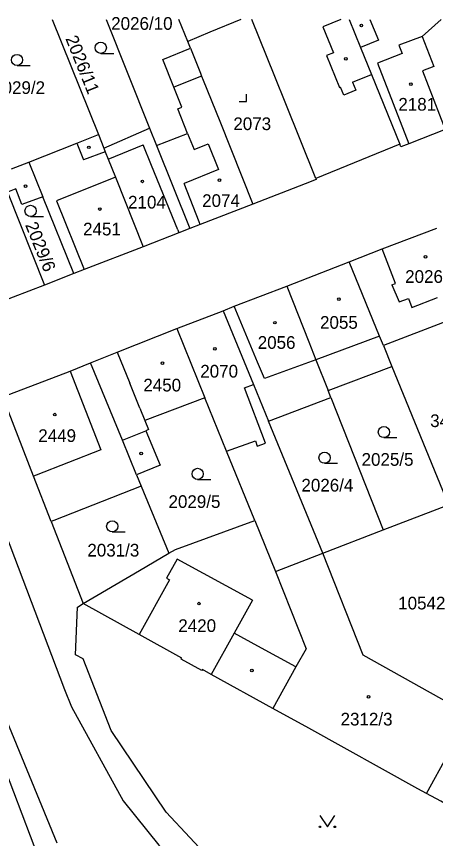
# Model space of a CAD drawing. Extents: x -564952 to -564307, y -1202373 to -1201847.
# Drawn here: x -564666.6 to -564610.5, y -1201959.8 to -1201849.7 of the extents above; entities that cross this region are included whole.
import ezdxf

# ---------------------------------------------------------------- set-up
doc = ezdxf.new("R2010")
doc.units = 0
for name, color, linetype in [('Hranice parcel', 7, 'Continuous'), ('Parcelní čísla', 7, 'Continuous'), ('Vnitřní kresba', 7, 'Continuous'), ('Značky budov', 7, 'Continuous'), ('Značky kultur', 7, 'Continuous')]:
    doc.layers.add(name, color=color, linetype=linetype)

msp = doc.modelspace()

# ---------------------------------------------------------------- linework, layer by layer
at = {"layer": 'Hranice parcel'}
for p, q in [((-564661.81, -1201850.07), (-564655.61, -1201865.52)), ((-564654.61, -1201850.07), (-564648.79, -1201864.64)), ((-564643.69, -1201853.02), (-564644.88, -1201850.07)), ((-564643.32, -1201853.94), (-564643.69, -1201853.02)), ((-564619.09, -1201857.46), (-564615.32, -1201866.78)), ((-564654.9, -1201867.35), (-564648.79, -1201864.64)), ((-564648.79, -1201864.64), (-564647.86, -1201866.96)), ((-564655.61, -1201865.52), (-564654.9, -1201867.35)), ((-564647.86, -1201866.96), (-564643.4, -1201878.11)), ((-564615.32, -1201866.78), (-564626.56, -1201871.38)), ((-564667.27, -1201870.1), (-564664.94, -1201869.19)), ((-564664.94, -1201869.19), (-564663.07, -1201873.83)), ((-564658.92, -1201884.13), (-564663.07, -1201873.83)), ((-564630.43, -1201885.8), (-564622.09, -1201882.54)), ((-564658.92, -1201884.13), (-564662.87, -1201885.69)), ((-564662.87, -1201885.69), (-564672.74, -1201889.5)), ((-564630.43, -1201885.8), (-564627.48, -1201893.3)), ((-564645.16, -1201891.48), (-564638.96, -1201889.11)), ((-564645.16, -1201891.48), (-564641.39, -1201900.77)), ((-564617.5, -1201893.79), (-564616.36, -1201896.58)), ((-564624.91, -1201899.78), (-564616.36, -1201896.58)), ((-564616.36, -1201896.58), (-564608.79, -1201915.11)), ((-564624.54, -1201900.73), (-564624.91, -1201899.78)), ((-564632.88, -1201903.92), (-564624.54, -1201900.73)), ((-564624.54, -1201900.73), (-564617.51, -1201918.49)), ((-564625.61, -1201921.62), (-564632.88, -1201903.92)), ((-564650.53, -1201911.09), (-564649.91, -1201912.6)), ((-564649.91, -1201912.6), (-564646.22, -1201921.62)), ((-564617.51, -1201918.49), (-564608.79, -1201915.11)), ((-564661.94, -1201917.34), (-564657.66, -1201928.36)), ((-564634.72, -1201917.22), (-564631.93, -1201924.07)), ((-564625.61, -1201921.62), (-564617.51, -1201918.49)), ((-564631.93, -1201924.07), (-564625.61, -1201921.62)), ((-564631.93, -1201924.07), (-564627.85, -1201934.4)), ((-564650.19, -1201932.49), (-564657.66, -1201928.36)), ((-564668.12, -1201950.64), (-564653.5, -1201989.14))]:
    msp.add_line(p, q, dxfattribs=at)
for points in [[(-564636.56, -1201850.07), (-564640.71, -1201851.79), (-564643.69, -1201853.02)], [(-564626.56, -1201871.38), (-564626.65, -1201871.15), (-564630.57, -1201861.4), (-564632.05, -1201857.71), (-564635.12, -1201850.07)], [(-564622.09, -1201850.07), (-564620.57, -1201853.84), (-564619.09, -1201857.46)], [(-564609.78, -1201850.07), (-564612.33, -1201852.38), (-564610.77, -1201856.4), (-564612.26, -1201856.98), (-564609.22, -1201864.81)], [(-564647.86, -1201866.96), (-564643.7, -1201865.35), (-564645.03, -1201862.07), (-564644.46, -1201861.84), (-564645.54, -1201859.17), (-564647.04, -1201855.43), (-564643.32, -1201853.94)], [(-564643.32, -1201853.94), (-564641.99, -1201857.29), (-564641.93, -1201857.43), (-564641.83, -1201857.68), (-564641.62, -1201858.2), (-564639.41, -1201863.69)], [(-564639.41, -1201863.69), (-564637.92, -1201867.4), (-564634.97, -1201874.82)], [(-564609.22, -1201864.81), (-564614.1, -1201866.74), (-564615.17, -1201867.16), (-564615.32, -1201866.78)], [(-564664.94, -1201869.19), (-564658.51, -1201866.66), (-564655.61, -1201865.52)], [(-564654.9, -1201867.35), (-564654.72, -1201867.8), (-564654.33, -1201868.79), (-564653.36, -1201871.21), (-564649.64, -1201880.53)], [(-564686.16, -1201871.23), (-564677.08, -1201895.29), (-564660.17, -1201939.88), (-564659.23, -1201942.17), (-564652.34, -1201954.8), (-564647.57, -1201960.74), (-564641.3, -1201967.43), (-564636.51, -1201971.74), (-564631.4, -1201974.9), (-564623.41, -1201978.76)], [(-564626.56, -1201871.38), (-564626.5, -1201871.52), (-564627.97, -1201872.09), (-564634.97, -1201874.82)], [(-564663.07, -1201873.83), (-564665.89, -1201874.89), (-564666.68, -1201872.79), (-564667.81, -1201873.23), (-564662.87, -1201885.69)], [(-564634.97, -1201874.82), (-564642, -1201877.55), (-564643.4, -1201878.11)], [(-564661.15, -1201960.44), (-564670.99, -1201936.66), (-564694.16, -1201875.63)], [(-564643.4, -1201878.11), (-564644.88, -1201878.68), (-564649.64, -1201880.53)], [(-564622.09, -1201882.54), (-564617.68, -1201880.84), (-564610.36, -1201878.05)], [(-564649.64, -1201880.53), (-564657.55, -1201883.6), (-564658.92, -1201884.13)], [(-564617.5, -1201893.79), (-564618.01, -1201892.54), (-564622.09, -1201882.54)], [(-564638.96, -1201889.11), (-564637.47, -1201888.5), (-564630.43, -1201885.8)], [(-564638.96, -1201889.11), (-564634.9, -1201899), (-564632.88, -1201903.92)], [(-564601.71, -1201917.21), (-564603.64, -1201912.23), (-564600.77, -1201911.06), (-564609.03, -1201890.5), (-564617.5, -1201893.79)], [(-564656.68, -1201896.09), (-564653.11, -1201894.66), (-564645.16, -1201891.48)], [(-564627.48, -1201893.3), (-564626.54, -1201895.68), (-564624.91, -1201899.78)], [(-564668.43, -1201900.65), (-564659.44, -1201897.19), (-564656.68, -1201896.09)], [(-564650.53, -1201911.09), (-564652.43, -1201906.46), (-564652.96, -1201905.18), (-564656.68, -1201896.09)], [(-564661.94, -1201917.34), (-564664.31, -1201911.26), (-564668.43, -1201900.65)], [(-564641.39, -1201900.77), (-564649.41, -1201903.83), (-564648.92, -1201905.05), (-564649.28, -1201905.19), (-564647.38, -1201909.8), (-564650.53, -1201911.09)], [(-564634.72, -1201917.22), (-564638.49, -1201907.91), (-564641.39, -1201900.77)], [(-564649.91, -1201912.6), (-564661.62, -1201917.21), (-564661.94, -1201917.34)], [(-564646.22, -1201921.62), (-564645.34, -1201921.1), (-564634.72, -1201917.22)], [(-564657.66, -1201928.36), (-564650.16, -1201923.94), (-564646.22, -1201921.62)], [(-564611.74, -1201953.8), (-564605.93, -1201943.27), (-564620.21, -1201935.26), (-564625.61, -1201921.62)], [(-564653.95, -1201945.36), (-564657.69, -1201935.77), (-564658.7, -1201935.2), (-564658.45, -1201928.82), (-564657.66, -1201928.36)], [(-564632.28, -1201942.4), (-564640.53, -1201937.84), (-564641.72, -1201937.18), (-564641.79, -1201937.31), (-564644.55, -1201935.78), (-564644.48, -1201935.65), (-564650.19, -1201932.49)], [(-564627.85, -1201934.4), (-564629.21, -1201936.85), (-564632.28, -1201942.4)], [(-564611.74, -1201953.8), (-564612.87, -1201953.17), (-564627.49, -1201945.06), (-564632.28, -1201942.4)], [(-564596.05, -1201977.38), (-564604.58, -1201977.37), (-564614.37, -1201976.21), (-564623.15, -1201973.61), (-564632.26, -1201969.32), (-564640.22, -1201963.11), (-564646.58, -1201956.32), (-564653.95, -1201945.36)], [(-564609.02, -1201955.3), (-564609.82, -1201954.85), (-564611.74, -1201953.8)]]:
    msp.add_lwpolyline(points, dxfattribs=at)
at = {"layer": 'Vnitřní kresba'}
for p, q in [((-564623.18, -1201850.07), (-564625.6, -1201851.05)), ((-564619.33, -1201850.07), (-564618.16, -1201852.86)), ((-564625.6, -1201851.05), (-564624.19, -1201854.54)), ((-564618.16, -1201852.86), (-564620.57, -1201853.84)), ((-564612.33, -1201852.38), (-564615.43, -1201853.51)), ((-564615.43, -1201853.51), (-564614.98, -1201854.65)), ((-564624.19, -1201854.54), (-564625.11, -1201854.91)), ((-564625.11, -1201854.91), (-564623.38, -1201859.2)), ((-564614.98, -1201854.65), (-564618.31, -1201855.95)), ((-564618.31, -1201855.95), (-564614.1, -1201866.74)), ((-564621.64, -1201858.5), (-564619.09, -1201857.46)), ((-564641.83, -1201857.68), (-564645.54, -1201859.17)), ((-564621.64, -1201858.5), (-564621.2, -1201859.58)), ((-564623.38, -1201859.2), (-564623.24, -1201859.14)), ((-564622.8, -1201860.23), (-564623.24, -1201859.14)), ((-564621.2, -1201859.58), (-564622.8, -1201860.23)), ((-564643.7, -1201865.35), (-564642.82, -1201867.52)), ((-564658.51, -1201866.66), (-564657.65, -1201868.91)), ((-564654.33, -1201868.79), (-564649.67, -1201866.89)), ((-564648.54, -1201869.67), (-564649.67, -1201866.89)), ((-564642.82, -1201867.52), (-564640.97, -1201866.77)), ((-564640.97, -1201866.77), (-564639.58, -1201870.19)), ((-564654.72, -1201867.8), (-564657.65, -1201868.91)), ((-564645.03, -1201878.28), (-564648.54, -1201869.67)), ((-564639.58, -1201870.19), (-564644.16, -1201872.06)), ((-564653.36, -1201871.21), (-564661.25, -1201874.37)), ((-564642.14, -1201877.18), (-564644.16, -1201872.06)), ((-564661.25, -1201874.37), (-564657.55, -1201883.6)), ((-564642, -1201877.55), (-564642.14, -1201877.18)), ((-564645.03, -1201878.28), (-564644.88, -1201878.68)), ((-564615.89, -1201885.45), (-564617.68, -1201880.84)), ((-564616.35, -1201885.64), (-564615.89, -1201885.45)), ((-564616.35, -1201885.64), (-564615.41, -1201887.93)), ((-564615.41, -1201887.93), (-564614.16, -1201887.47)), ((-564614.16, -1201887.47), (-564613.7, -1201888.69)), ((-564613.7, -1201888.69), (-564610.28, -1201887.35)), ((-564634.33, -1201895.99), (-564637.47, -1201888.5)), ((-564618.01, -1201892.54), (-564626.54, -1201895.68)), ((-564653.11, -1201894.66), (-564651.43, -1201898.82)), ((-564633.4, -1201898.2), (-564634.33, -1201895.99)), ((-564626.54, -1201895.68), (-564633.4, -1201898.2)), ((-564659.44, -1201897.19), (-564655.32, -1201907.74)), ((-564650.09, -1201902.15), (-564651.43, -1201898.82)), ((-564636.11, -1201899.46), (-564634.9, -1201899)), ((-564633.26, -1201906.88), (-564636.11, -1201899.46)), ((-564650.09, -1201902.15), (-564649.41, -1201903.83)), ((-564652.43, -1201906.46), (-564649.28, -1201905.19)), ((-564638.49, -1201907.91), (-564634.63, -1201906.56)), ((-564634.63, -1201906.56), (-564634.38, -1201907.27)), ((-564634.38, -1201907.27), (-564633.26, -1201906.88)), ((-564655.32, -1201907.74), (-564663.98, -1201911.13)), ((-564663.98, -1201911.13), (-564664.31, -1201911.26)), ((-564645.1, -1201922.41), (-564646.52, -1201924.96)), ((-564635.02, -1201927.88), (-564645.1, -1201922.41)), ((-564646.14, -1201925.17), (-564650.19, -1201932.49)), ((-564646.52, -1201924.96), (-564646.14, -1201925.17)), ((-564635.02, -1201927.88), (-564637.48, -1201932.32)), ((-564637.48, -1201932.32), (-564640.53, -1201937.84)), ((-564634.32, -1201934.04), (-564637.48, -1201932.32)), ((-564629.21, -1201936.85), (-564634.32, -1201934.04))]:
    msp.add_line(p, q, dxfattribs=at)
at = {"layer": 'Značky budov'}
for centre in [(-564620.45, -1201850.89), (-564622.53, -1201855.36), (-564613.81, -1201858.76), (-564656.91, -1201867.22), (-564649.76, -1201871.78), (-564639.45, -1201871.62), (-564665.38, -1201872.42), (-564655.44, -1201875.49), (-564611.87, -1201881.89), (-564623.45, -1201887.56), (-564632.01, -1201890.71), (-564640.04, -1201894.22), (-564647.08, -1201896.15), (-564661.49, -1201903.03), (-564649.92, -1201908.25), (-564642.18, -1201928.36), (-564635.09, -1201937.32), (-564619.48, -1201940.85)]:
    msp.add_circle(centre, 0.175, dxfattribs=at)
at = {"layer": 'Značky kultur'}
for p, q in [((-564655.32, -1201854.63), (-564653.57, -1201854.63)), ((-564666.53, -1201856.26), (-564664.78, -1201856.26)), ((-564635.8, -1201861.08), (-564635.8, -1201860.08)), ((-564636.8, -1201861.08), (-564635.8, -1201861.08)), ((-564664.72, -1201876.48), (-564662.97, -1201876.48)), ((-564617.43, -1201906.12), (-564615.68, -1201906.12)), ((-564625.38, -1201909.56), (-564623.63, -1201909.56)), ((-564642.36, -1201911.72), (-564640.61, -1201911.72)), ((-564653.79, -1201918.75), (-564652.04, -1201918.75))]:
    msp.add_line(p, q, dxfattribs=at)
msp.add_lwpolyline([(-564626, -1201956.77), (-564625, -1201958.27), (-564624, -1201956.77)], dxfattribs=at)
for centre, radius in [((-564655.32, -1201853.88), 0.75), ((-564666.53, -1201855.51), 0.75), ((-564664.72, -1201875.73), 0.75), ((-564617.43, -1201905.37), 0.75), ((-564625.38, -1201908.81), 0.75), ((-564642.36, -1201910.97), 0.75), ((-564653.79, -1201918), 0.75), ((-564626, -1201958.27), 0.1), ((-564624, -1201958.27), 0.1)]:
    msp.add_circle(centre, radius, dxfattribs=at)

# ---------------------------------------------------------------- texts
at = {"layer": 'Parcelní čísla'}
for s, p in [('2026/10', (-564653.93, -1201851.47)), ('2029/2', (-564669.73, -1201860.07)), ('2181', (-564615.5, -1201862.3)), ('2073', (-564637.58, -1201864.91)), ('2104', (-564651.67, -1201875.42)), ('2074', (-564641.76, -1201875.21)), ('2451', (-564657.69, -1201879.02)), ('2026', (-564614.59, -1201885.38)), ('2055', (-564625.98, -1201891.53)), ('2056', (-564634.32, -1201894.22)), ('2070', (-564642.01, -1201898.07)), ('2450', (-564649.63, -1201899.93)), ('3489', (-564611.24, -1201904.7)), ('2449', (-564663.69, -1201906.7)), ('2025/5', (-564620.42, -1201909.89)), ('2026/4', (-564628.47, -1201913.34)), ('2029/5', (-564646.26, -1201915.54)), ('2031/3', (-564657.12, -1201922.05)), ('10542', (-564615.52, -1201929.14)), ('2420', (-564644.95, -1201932.16)), ('2312/3', (-564623.23, -1201944.69))]:
    msp.add_text(s, height=1.7, dxfattribs=at).set_placement(p)
for s, p in [('2026/11', (-564660.09, -1201852.63)), ('2029/6', (-564665.47, -1201877.61))]:
    msp.add_text(s, height=1.7, rotation=292, dxfattribs=at).set_placement(p)

doc.saveas('drawing.dxf')
